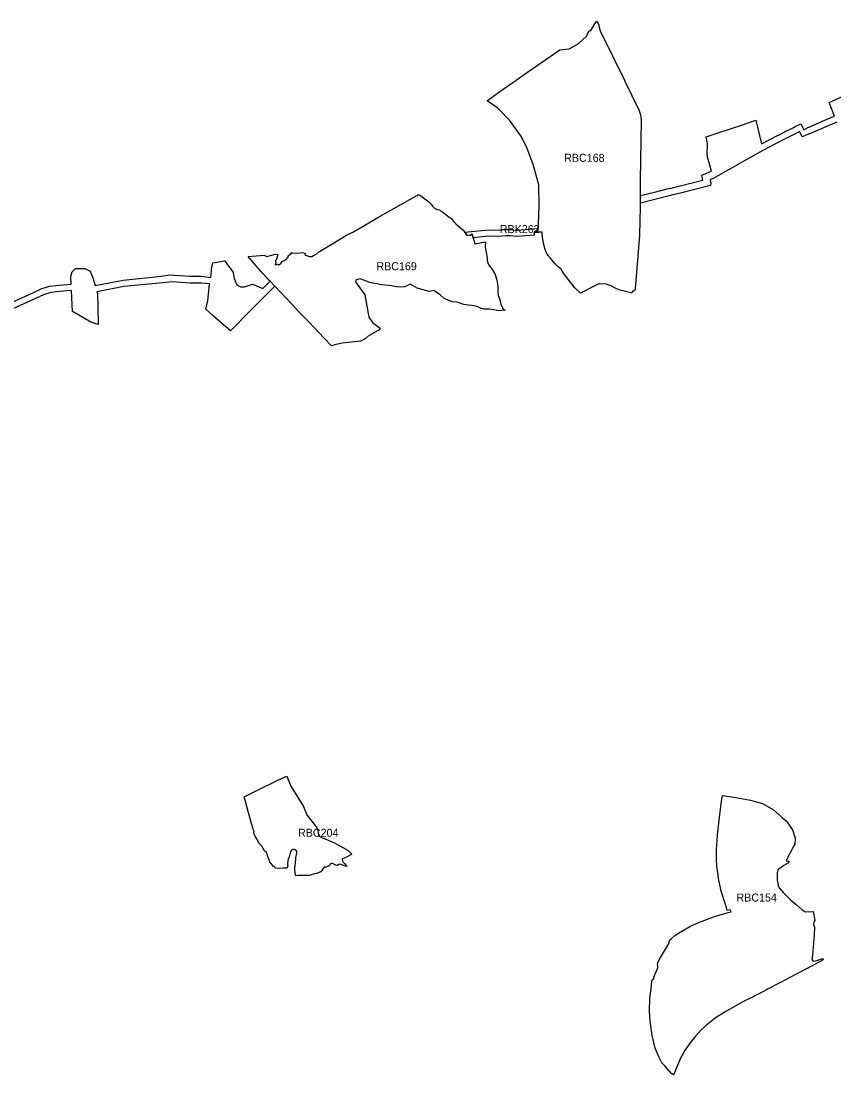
# Model space of a CAD drawing. Extents: x -559776 to -467147, y -1204122 to -1132159.
# Drawn here: x -537061 to -531983, y -1169149 to -1162564 of the extents above; entities that cross this region are included whole.
import ezdxf

# ---------------------------------------------------------------- set-up
doc = ezdxf.new("R2010")
doc.units = 0
doc.layers.add('regionalni_biocentrum_biokoridor', color=7, linetype='Continuous')

msp = doc.modelspace()

# ---------------------------------------------------------------- linework, layer by layer
at = {"layer": 'regionalni_biocentrum_biokoridor'}
for points in [[(-533210.67, -1164058.92), (-533224.4, -1164235.21), (-533225.17, -1164241.13), (-533225.37, -1164242.71), (-533230.35, -1164246.69), (-533231.46, -1164249.46), (-533234.78, -1164251.39), (-533241.42, -1164251.39), (-533241.57, -1164252.89), (-533242.1, -1164258.15), (-533249.97, -1164262.45), (-533285.89, -1164254.36), (-533286.17, -1164254.3), (-533319.13, -1164245.25), (-533341.23, -1164236.19), (-533374.55, -1164218.8), (-533395.2, -1164211.19), (-533404.25, -1164208.29), (-533448.81, -1164205.4), (-533451.23, -1164205.11), (-533477.53, -1164218.54), (-533565.93, -1164263.68), (-533602.82, -1164230.12), (-533640.27, -1164182.23), (-533673.7, -1164139.23), (-533687.68, -1164114.87), (-533688.17, -1164114.09), (-533706.71, -1164099.61), (-533720.75, -1164085.57), (-533728.8, -1164077.51), (-533754.16, -1164045.63), (-533769.73, -1164027.05), (-533774.8, -1164021), (-533784.95, -1163998.17), (-533797.62, -1163952.89), (-533805.59, -1163897.1), (-533806.24, -1163883.64), (-533835.29, -1163881.93), (-533832.78, -1163859.55), (-533829.54, -1163830.58), (-533824.14, -1163715.97), (-533826.84, -1163586.52), (-533861.94, -1163461.11), (-533901.09, -1163354.58), (-533940.25, -1163281.22), (-534010.45, -1163182.78), (-534082, -1163107.27), (-534149.5, -1163061.42), (-534076.6, -1163007.49), (-534050.46, -1162989.46), (-533983.12, -1162943.03), (-533924.05, -1162902.31), (-533695.08, -1162744.54), (-533638.38, -1162737.8), (-533580.32, -1162705.43), (-533526.32, -1162655.54), (-533514.17, -1162627.22), (-533502.02, -1162623.18), (-533476.64, -1162581.87), (-533476, -1162581.6), (-533471.97, -1162574.26), (-533465.57, -1162563.85), (-533452.3, -1162587.85), (-533451.73, -1162596.46), (-533444.1, -1162624.46), (-533290.57, -1162938.01), (-533289.84, -1162939.51), (-533202.72, -1163117.86), (-533193.53, -1163143.64), (-533190.14, -1163160.57), (-533188.36, -1163188), (-533192.98, -1163559.01), (-533193, -1163560.51), (-533193.14, -1163569.73), (-533193.78, -1163591.71), (-533194.13, -1163654.68), (-533194.39, -1163701.03), (-533194.52, -1163723.88), (-533198.27, -1163899.7), (-533198.38, -1163901.2)], [(-534289.68, -1163882.57), (-534274.11, -1163904.54), (-534252.83, -1163901.63), (-534244.76, -1163892.43), (-534237.67, -1163917.64), (-534227.08, -1163955.31), (-534159.73, -1163943.45), (-534161.5, -1163976.09), (-534155.36, -1164009.53), (-534149.21, -1164042.98), (-534149.21, -1164059.79), (-534145.4, -1164075.27), (-534139.09, -1164090.21), (-534131.74, -1164100.23), (-534119.98, -1164111.82), (-534100.58, -1164147.39), (-534089.78, -1164183.26), (-534082.23, -1164219.65), (-534083.63, -1164255.5), (-534079.96, -1164278.6), (-534077.87, -1164283.78), (-534071.98, -1164296.52), (-534063.83, -1164331.97), (-534057.94, -1164347.94), (-534050.73, -1164362.2), (-534037.47, -1164370.71), (-534077.93, -1164375.51), (-534117.71, -1164365.91), (-534135.54, -1164363.86), (-534146.51, -1164364.54), (-534169.14, -1164364.54), (-534190.4, -1164357.68), (-534212.59, -1164347.74), (-534243.2, -1164341.91), (-534265.83, -1164339.17), (-534295.32, -1164335.05), (-534336.46, -1164319.97), (-534367.32, -1164319.28), (-534418.75, -1164298.02), (-534441.53, -1164276.82), (-534482.53, -1164246.59), (-534512.7, -1164252.76), (-534587.45, -1164233.56), (-534630.4, -1164207.78), (-534663.54, -1164225.41), (-534704.16, -1164226.38), (-534762.72, -1164216.26), (-534809.19, -1164212.22), (-534884.45, -1164197.82), (-534940.02, -1164175.33), (-534968.31, -1164179.87), (-534971.92, -1164194.3), (-534914.18, -1164273.95), (-534888.99, -1164413.7), (-534866.73, -1164446.89), (-534817.51, -1164482.62), (-534825.16, -1164493.56), (-534893.79, -1164532.72), (-534912.69, -1164548.82), (-534922.77, -1164555.8), (-534931.83, -1164560.33), (-534941.04, -1164563.14), (-534998.01, -1164569.61), (-535054.98, -1164576.08), (-535101.51, -1164586.86), (-535121.32, -1164593.68), (-535123.83, -1164591.05), (-535167.12, -1164545.6), (-535266.37, -1164441.4), (-535331.64, -1164373.77), (-535334.79, -1164370.11), (-535405.08, -1164295.65), (-535475.37, -1164221.18), (-535476.48, -1164220.16), (-535477.83, -1164218.92), (-535506.15, -1164189.48), (-535515.37, -1164179.9), (-535546.6, -1164146.25), (-535551.35, -1164141.24), (-535594.2, -1164091.23), (-535643.69, -1164035.92), (-535542.79, -1164026.8), (-535525.88, -1164034.07), (-535471.1, -1164021.18), (-535458.2, -1164022.96), (-535465.62, -1164053.27), (-535471.25, -1164060.39), (-535470.07, -1164072.11), (-535473.33, -1164086.66), (-535457.32, -1164082.95), (-535450.2, -1164087.4), (-535438.64, -1164078.35), (-535429.75, -1164066.77), (-535406.84, -1164055.42), (-535392.46, -1164039.84), (-535392.76, -1164031.08), (-535372.15, -1164015.05), (-535375.26, -1164012.06), (-535365.56, -1164011.38), (-535335.49, -1164013.26), (-535305.36, -1164009.95), (-535287.07, -1164014.13), (-535287.95, -1164024.73), (-535262.3, -1164034.97), (-535245.32, -1164034.31), (-535233.83, -1164028.53), (-535222.34, -1164022.74), (-535214.97, -1164017.71), (-535212.35, -1164016.47), (-535200.96, -1164006.21), (-535197.73, -1164003.57), (-535155.38, -1163978.73), (-535113.04, -1163953.89), (-535028.45, -1163902.3), (-535011.78, -1163892.63), (-534988.48, -1163882.4), (-534910.23, -1163837.25), (-534831.99, -1163792.11), (-534750.88, -1163745.1), (-534599.53, -1163660.86), (-534594.8, -1163656.3), (-534583.51, -1163653.39), (-534579.51, -1163648.1), (-534563.85, -1163655.39), (-534514.58, -1163692.37), (-534499.11, -1163708.04), (-534491.82, -1163721.17), (-534477.72, -1163733.47), (-534462.61, -1163741.31), (-534447.86, -1163744.23), (-534442.76, -1163746.6), (-534429.1, -1163756.76), (-534397.55, -1163780.58), (-534365.99, -1163804.4), (-534358.15, -1163818.07), (-534344.04, -1163834), (-534298.89, -1163869.57)], [(-533835.29, -1163881.93), (-533836.07, -1163881.89), (-533845.44, -1163881.34), (-533856.09, -1163881.75), (-533855.44, -1163901.69), (-533962.22, -1163911.06), (-534004.94, -1163906.1), (-534035.41, -1163906.74), (-534077.67, -1163909.71), (-534122.92, -1163907.57), (-534161.03, -1163910.1), (-534237.67, -1163917.64), (-534244.76, -1163892.43), (-534252.83, -1163901.63), (-534274.11, -1163904.54), (-534289.68, -1163882.57), (-534164.31, -1163870.23), (-534123.3, -1163867.51), (-534078.13, -1163869.65), (-534037.24, -1163866.77), (-534003.04, -1163866.06), (-533961.65, -1163870.86), (-533832.78, -1163859.55)], [(-535102.89, -1167699.06), (-535018.69, -1167746.02), (-534995.31, -1167770.42), (-534997.87, -1167772.25), (-535009, -1167778.06), (-535023.51, -1167786.28), (-535042.38, -1167794.03), (-535054.96, -1167798.87), (-535056.32, -1167802.74), (-535053.9, -1167811.45), (-535050.02, -1167819.2), (-535041.32, -1167828.88), (-535032.13, -1167837.59), (-535026.8, -1167844.37), (-535027.29, -1167846.3), (-535033.09, -1167845.33), (-535041.32, -1167842.91), (-535058.25, -1167836.62), (-535069.86, -1167832.75), (-535076.63, -1167835.17), (-535086.79, -1167840.49), (-535094.53, -1167839.53), (-535103.24, -1167834.2), (-535115.34, -1167828.39), (-535125.01, -1167828.39), (-535128.66, -1167830.83), (-535130.82, -1167832.27), (-535135.17, -1167840.98), (-535144.37, -1167847.27), (-535155.01, -1167850.66), (-535168.07, -1167851.63), (-535176.15, -1167861.31), (-535182.44, -1167871.23), (-535188.73, -1167881.15), (-535214.85, -1167890.35), (-535236.14, -1167894.7), (-535246.78, -1167899.54), (-535262.19, -1167902.88), (-535328.82, -1167904.15), (-535330.94, -1167904.19), (-535345.3, -1167904.47), (-535347.56, -1167900.51), (-535350.94, -1167868.91), (-535350.24, -1167849.18), (-535348.72, -1167843.09), (-535347.13, -1167822.08), (-535346, -1167801.75), (-535345.16, -1167790.17), (-535340.93, -1167773.24), (-535338.95, -1167761.95), (-535339.23, -1167755.46), (-535341.49, -1167749.53), (-535346.57, -1167745.02), (-535355.03, -1167741.35), (-535362.94, -1167740.5), (-535369.43, -1167742.76), (-535376.2, -1167750.1), (-535382.97, -1167770.42), (-535387.49, -1167786.5), (-535392, -1167802.02), (-535394.26, -1167808.52), (-535394.39, -1167809.15), (-535395.39, -1167814.16), (-535396.11, -1167826.83), (-535396.52, -1167833.91), (-535395.39, -1167844.92), (-535396.52, -1167850), (-535399.06, -1167855.36), (-535402.73, -1167857.05), (-535411.11, -1167856.82), (-535412.61, -1167856.77), (-535421.35, -1167857.34), (-535443.93, -1167859.59), (-535469.89, -1167857.05), (-535473.73, -1167855.62), (-535475.14, -1167852.23), (-535477.68, -1167849.12), (-535481.07, -1167847.71), (-535484.89, -1167846.2), (-535508.28, -1167817.65), (-535509.57, -1167809.31), (-535512.11, -1167804.23), (-535516.64, -1167797.39), (-535523.69, -1167769.49), (-535529.4, -1167757.33), (-535539.7, -1167749.5), (-535556.5, -1167719.96), (-535576.63, -1167700.26), (-535587.99, -1167673.45), (-535598.65, -1167656.81), (-535606.11, -1167644.65), (-535606.33, -1167631.91), (-535606.01, -1167628.61), (-535605.69, -1167625.3), (-535610.89, -1167612.98), (-535640.36, -1167511.49), (-535662.27, -1167433.25), (-535667.57, -1167413.21), (-535664.16, -1167409.06), (-535630.6, -1167392.88), (-535597.03, -1167376.7), (-535546.4, -1167351.38), (-535512.06, -1167334.58), (-535453.2, -1167305.79), (-535401.78, -1167282.47), (-535376.36, -1167345.33), (-535297.92, -1167471.91), (-535276.53, -1167524.92), (-535223.44, -1167589.79), (-535215.42, -1167599.79), (-535208.23, -1167622.6), (-535202.73, -1167651.33), (-535197.65, -1167659.77)], [(-532490.61, -1167436.45), (-532430.14, -1167453.99), (-532361.51, -1167493.84), (-532304.64, -1167542.43), (-532282.01, -1167561.78), (-532241.37, -1167618.25), (-532226.36, -1167669.42), (-532227.43, -1167707.72), (-532233.89, -1167717.61), (-532282.16, -1167810.12), (-532280, -1167812.71), (-532267.07, -1167810.98), (-532263.63, -1167815.72), (-532267.07, -1167823.46), (-532296.38, -1167840.24), (-532311.03, -1167850.14), (-532332.14, -1167864.77), (-532337.31, -1167887.14), (-532337.75, -1167931.03), (-532331.28, -1167965.89), (-532325.25, -1167981.1), (-532298.53, -1168011.66), (-532295.15, -1168015.04), (-532286.5, -1168023.68), (-532280.97, -1168029.2), (-532277.06, -1168033.11), (-532273.96, -1168036.2), (-532257.16, -1168052.98), (-532220.1, -1168083.97), (-532182.18, -1168117.11), (-532160.34, -1168131.23), (-532112.5, -1168128.22), (-532102.16, -1168182.88), (-532103.11, -1168184.58), (-532106.54, -1168190.75), (-532108.63, -1168194.5), (-532110.35, -1168208.7), (-532103.89, -1168225.06), (-532106.47, -1168275.42), (-532114.23, -1168375.45), (-532118.97, -1168418.49), (-532118.54, -1168430.97), (-532112.94, -1168438.29), (-532089.23, -1168433.55), (-532053.47, -1168422.36), (-532050.02, -1168429.25), (-532120.26, -1168467.12), (-532249.54, -1168535.99), (-532313.44, -1168569.43), (-532402.83, -1168616.21), (-532407.71, -1168618.76), (-532424.32, -1168627.45), (-532478.22, -1168655.34), (-532484.68, -1168658.68), (-532555.75, -1168695.46), (-532609.7, -1168725.24), (-532663.65, -1168755.03), (-532724.84, -1168795.05), (-532778.27, -1168835.94), (-532813.18, -1168868.65), (-532846.36, -1168905.24), (-532882.56, -1168950), (-532914.27, -1168997.05), (-532941.42, -1169045.25), (-532967.71, -1169104.65), (-532983.65, -1169147.26), (-532986.24, -1169149.41), (-532995.72, -1169142.96), (-533041.82, -1169090.45), (-533058.63, -1169073.23), (-533075.87, -1169040.95), (-533099.14, -1168981.55), (-533118.79, -1168903.86), (-533131.71, -1168814.34), (-533134.73, -1168751.5), (-533134.3, -1168667.87), (-533125.68, -1168613.21), (-533122.23, -1168583.94), (-533118.79, -1168554.67), (-533110.24, -1168550.5), (-533104.47, -1168528.48), (-533083.75, -1168480.53), (-533083.27, -1168472.48), (-533084.9, -1168457.16), (-533080.34, -1168442.83), (-533066.05, -1168415.28), (-533017.12, -1168331.9), (-533007.64, -1168304.62), (-533001.14, -1168298.47), (-532976.67, -1168278.81), (-532944.05, -1168256.34), (-532882.86, -1168221.02), (-532822.1, -1168194.34), (-532729.45, -1168159.9), (-532650.76, -1168136.88), (-532644.79, -1168135.31), (-532626.2, -1168130.42), (-532631.37, -1168117.08), (-532649.37, -1168122.33), (-532651.55, -1168116.15), (-532655.29, -1168102.72), (-532689.07, -1167995.09), (-532690.59, -1167990.17), (-532704.06, -1167922.75), (-532709.43, -1167884.52), (-532713.94, -1167845.47), (-532716.04, -1167802.51), (-532716.31, -1167741.18), (-532713.22, -1167682.41), (-532709.76, -1167649.29), (-532695.58, -1167522.71), (-532685.68, -1167438.35), (-532679.49, -1167403.51), (-532597.07, -1167414.94), (-532572.58, -1167419.57), (-532504.46, -1167432.44)]]:
    msp.add_lwpolyline(points, close=True, dxfattribs=at)
for points in [[(-531964.83, -1163194.94), (-531990.38, -1163205.84), (-532126.03, -1163264.49), (-532153.14, -1163275.03), (-532180.09, -1163286.84), (-532181.36, -1163284.1), (-532198.24, -1163254.2), (-532204.62, -1163257.55), (-532213.3, -1163262.1), (-532217.11, -1163264.1), (-532217.42, -1163264.24), (-532217.6, -1163264.33), (-532217.79, -1163264.42), (-532217.96, -1163264.53), (-532218.14, -1163264.64), (-532305.41, -1163307.96), (-532312.34, -1163311.93), (-532426.46, -1163372.12), (-532582.86, -1163459.58), (-532586.35, -1163461.57), (-532660.02, -1163503.62), (-532733.87, -1163545.27), (-532735.61, -1163547.39), (-532742.52, -1163549.45), (-532749.81, -1163551.63), (-532757.49, -1163554.78), (-532752.8, -1163580.22), (-532754.27, -1163591.69), (-532941.74, -1163638.77), (-532989.63, -1163650.68), (-533013.28, -1163656.54), (-533093.21, -1163676.62), (-533192.59, -1163700.99), (-533191.77, -1163654.44), (-533103.96, -1163632.93), (-533024.17, -1163612.88), (-533000.47, -1163607.01), (-532952.65, -1163595.11), (-532802.75, -1163557.47), (-532808.36, -1163527.03), (-532761.83, -1163507.92), (-532747.24, -1163501.92), (-532758.81, -1163463.57), (-532773.25, -1163414.64), (-532773.76, -1163410.67), (-532774.78, -1163395.96), (-532772.78, -1163332.3), (-532775.02, -1163316.27), (-532780.45, -1163287.52), (-532668.18, -1163249.69), (-532653.85, -1163244.86), (-532555.17, -1163211.94), (-532490.5, -1163190.09), (-532471.89, -1163183.97), (-532436.15, -1163332), (-532330.71, -1163276.39), (-532330.06, -1163276.06), (-532321.51, -1163271.73), (-532279.71, -1163250.55), (-532238.71, -1163230.19), (-532236.33, -1163229.01), (-532224.69, -1163222.9), (-532221.1, -1163221.02), (-532190.7, -1163205.07), (-532171.75, -1163242.87), (-532141.22, -1163227.48), (-532137.95, -1163226.06), (-532125.15, -1163220.53), (-532006.16, -1163169.09), (-531979.28, -1163157.62), (-532013.29, -1163071.8), (-531812.11, -1162982)], [(-537437.23, -1164464.97), (-537015.9, -1164274.08), (-536935.13, -1164237.1), (-536883.34, -1164220.47), (-536824.53, -1164213.35), (-536748.45, -1164207.73), (-536750.49, -1164159.85), (-536742.3, -1164130.38), (-536720.99, -1164110.73), (-536663.61, -1164109.09), (-536630.83, -1164127.1), (-536612.8, -1164168.04), (-536598.87, -1164217.16), (-536424.46, -1164182.77), (-536184.2, -1164157.22), (-536133.74, -1164150.43), (-536006.62, -1164157.22), (-535933.84, -1164158.19), (-535875.68, -1164166.13), (-535871.92, -1164122.3), (-535871.2, -1164114.97), (-535865.6, -1164082.96), (-535863.87, -1164075.3), (-535800.64, -1164063.74), (-535789.25, -1164063.09), (-535772.75, -1164087.35), (-535754.32, -1164108.7), (-535736.85, -1164135.87), (-535729.41, -1164173.19), (-535714.53, -1164211.56), (-535691.24, -1164224.18), (-535665.04, -1164225.15), (-535616.52, -1164207.68), (-535550.53, -1164235.82), (-535506.15, -1164189.48), (-535477.83, -1164218.92), (-535476.48, -1164220.16), (-535619.62, -1164363.94), (-535619.2, -1164364.25), (-535753.21, -1164498.66), (-535859.72, -1164407.69), (-535906.67, -1164363.91), (-535894.05, -1164311.51), (-535883.38, -1164205.74), (-535933.84, -1164200.89), (-536004.68, -1164200.89), (-536118.21, -1164193.12), (-536176.44, -1164199.92), (-536419.26, -1164222.52), (-536587.91, -1164255.77), (-536584.93, -1164266.27), (-536581.65, -1164353.05), (-536580.01, -1164459.48), (-536621.62, -1164448.35), (-536741.14, -1164378.95), (-536746.74, -1164247.71), (-536820.65, -1164253.18), (-536874.74, -1164259.72), (-536920.64, -1164274.46), (-536999.32, -1164310.48), (-537421.77, -1164501.88)]]:
    msp.add_lwpolyline(points, dxfattribs=at)

# ---------------------------------------------------------------- texts
for s, p in [('RBC168', (-533668.93, -1163443.4)), ('RBK262', (-534070.64, -1163888.6)), ('RBC169', (-534841.91, -1164120.89)), ('RBC204', (-535331.44, -1167661.01)), ('RBC154', (-532592.38, -1168065.75))]:
    msp.add_text(s, height=50, dxfattribs=at).set_placement(p)

doc.saveas('drawing.dxf')
